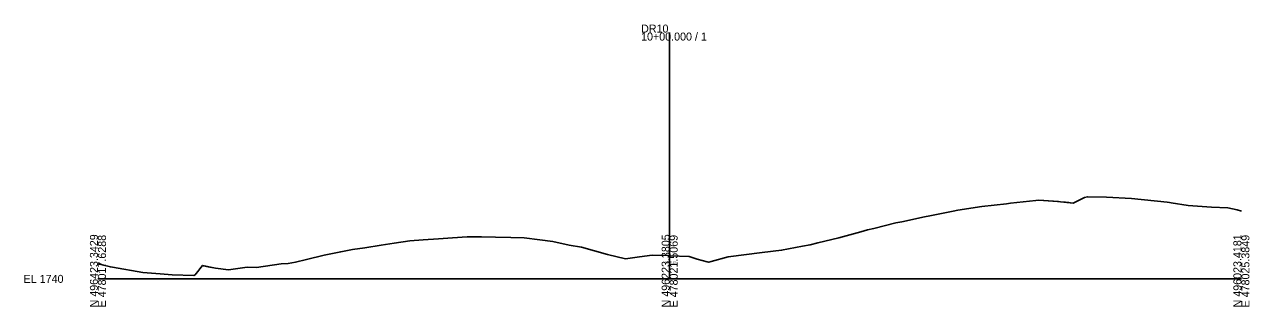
# Model space of a CAD drawing. Extents: x -26 to 403, y -10 to 2062.
# Drawn here: x -25.7 to 402.8, y -9.7 to 89.1 of the extents above; entities that cross this region are included whole.
import ezdxf

# ---------------------------------------------------------------- set-up
doc = ezdxf.new("R2010")
doc.units = 0
for name, color, linetype in [('Exist Cross Section Cell', 7, 'Continuous'), ('Exist XS Center Line Elevation Label', 7, 'Continuous'), ('Exist XS Ground Line', 7, 'Continuous'), ('Scratch_Level_5', 7, 'Continuous')]:
    doc.layers.add(name, color=color, linetype=linetype)

msp = doc.modelspace()

# ---------------------------------------------------------------- linework, layer by layer
at = {"layer": 'Exist Cross Section Cell'}
for p, q in [((200, 0), (200, 86.28)), ((0, 0), (200, 0)), ((200, 0), (400, 0))]:
    msp.add_line(p, q, dxfattribs=at)
at = {"layer": 'Exist XS Ground Line'}
msp.add_lwpolyline([(0, 5.22), (3.93, 4.28), (4.37, 4.17), (5.12, 4.05), (15.75, 2.23), (21.74, 1.81), (25.95, 1.42), (33.54, 1.13), (34.02, 1.43), (34.38, 1.89), (34.89, 2.54), (35.64, 3.48), (36.59, 4.69), (36.92, 4.62), (38.02, 4.38), (39.11, 4.15), (40.5, 3.85), (41.13, 3.71), (45.7, 3.19), (52.2, 4.06), (55.52, 3.97), (64.11, 5.26), (66.57, 5.39), (69.09, 5.9), (73, 6.83), (79.09, 8.29), (84.96, 9.52), (89.1, 10.27), (93.4, 10.91), (99.1, 11.8), (103.6, 12.49), (109.1, 13.31), (113.8, 13.63), (119.11, 13.99), (124, 14.35), (129.11, 14.67), (134.21, 14.69), (139.11, 14.66), (144.41, 14.46), (149.12, 14.38), (154.61, 13.62), (159.12, 13.12), (164.81, 11.85), (169.13, 11.08), (178.28, 8.49), (184.56, 7.02), (189.44, 7.77), (193.86, 8.29), (199.26, 8.16), (200, 8.12), (206.84, 7.78), (208.57, 7.25), (209.62, 6.94), (213.11, 5.93), (213.7, 5.82), (214.51, 6.04), (220.48, 7.77), (232.4, 9.21), (239.15, 10), (246.42, 11.41), (249.16, 11.95), (251.79, 12.59), (259.16, 14.42), (266.83, 16.53), (269.16, 17.19), (271.41, 17.69), (279.17, 19.58), (281.23, 20.01), (289.17, 21.74), (291.04, 22.1), (299.18, 23.76), (300.85, 24.02), (309.18, 25.4), (317.84, 26.28), (319.18, 26.47), (328.04, 27.4), (329.19, 27.55), (336, 27.11), (336.76, 27.03), (338.15, 26.87), (338.51, 26.83), (339.67, 26.7), (340.18, 26.64), (341.13, 26.53), (345.15, 28.54), (346.15, 28.76), (352.83, 28.63), (361.55, 28.12), (374.05, 26.86), (374.8, 26.78), (375.41, 26.67), (381.36, 25.71), (389.58, 25.11), (395.28, 24.83), (398.57, 24.17), (400, 23.72)], dxfattribs=at)
at = {"layer": 'Scratch_Level_5'}
msp.add_lwpolyline([(36.59, 4.69), (41.13, 3.71), (45.7, 3.19), (52.2, 4.06), (55.52, 3.97), (64.11, 5.26), (66.57, 5.39), (69.09, 5.9), (73, 6.83), (79.09, 8.29), (84.96, 9.52), (89.1, 10.27), (93.4, 10.91), (99.1, 11.8), (103.6, 12.49), (109.1, 13.31), (113.8, 13.63), (119.11, 13.99), (124, 14.35), (129.11, 14.67), (134.21, 14.69), (139.11, 14.66), (144.41, 14.46), (149.12, 14.38), (154.61, 13.62), (159.12, 13.12), (164.81, 11.85), (169.13, 11.08), (178.28, 8.49), (184.56, 7.02), (189.44, 7.77), (193.86, 8.29), (199.26, 8.16), (200, 8.12), (206.84, 7.78), (208.57, 7.25), (209.62, 6.94), (213.11, 5.93), (213.7, 5.82), (214.51, 6.04), (220.48, 7.77), (232.4, 9.21), (239.15, 10), (246.42, 11.41), (249.16, 11.95), (251.79, 12.59), (259.16, 14.42), (266.83, 16.53), (269.16, 17.19), (271.41, 17.69), (279.17, 19.58), (281.23, 20.01), (289.17, 21.74), (291.04, 22.1), (299.18, 23.76), (300.85, 24.02), (309.18, 25.4), (317.84, 26.28), (319.18, 26.47), (328.04, 27.4), (329.19, 27.55), (335.62, 27.16), (341.13, 26.53)], dxfattribs=at)

# ---------------------------------------------------------------- texts
at = {"layer": 'Exist Cross Section Cell'}
for s, p in [('10+00.000 / 1', (190, 83.48)), ('DR10', (190, 86.28)), ('EL 1740', (-26, -1.4))]:
    msp.add_text(s, height=2.8, dxfattribs=at).set_placement(p)
for s, p in [('N 496423.3429', (0, -10)), ('E 478017.6288', (2.8, -10)), ('N 496223.3805', (200, -10)), ('E 478021.5069', (202.8, -10)), ('N 496023.4181', (400, -10)), ('E 478025.3849', (402.8, -10))]:
    msp.add_text(s, height=2.8, rotation=90, dxfattribs=at).set_placement(p)
at = {"layer": 'Exist XS Center Line Elevation Label'}
msp.add_text('1748.12', height=0.75, dxfattribs=at).set_placement((198.42, 5.37))

doc.saveas('drawing.dxf')
